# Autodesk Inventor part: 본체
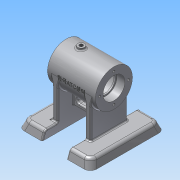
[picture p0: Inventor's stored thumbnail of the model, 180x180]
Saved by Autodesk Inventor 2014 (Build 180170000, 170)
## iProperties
Created: 2016-07
Part Number: 본체
Material: 알루미늄 6061
Document SubType Name: Modeling
Designer: Administrator
Density: 2.71 g/cm^3
Appearance: 알루미늄 - 평지
Mass: 512.163 g
Surface Area: 537.388 cm^2
Volume: 188.99 cm^3
Author: Administrator
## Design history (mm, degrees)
sketch "스케치1"
  geometry: C1 r 27 at (0, 0); 1 further point
  constraints: 1 centre point, 1 coincident
  dimensions: "d0" = 54 diameter of C1
extrude "돌출1" new body sketch "스케치1" stored distance "d1" = 70; taper "d2" = 0 deg
sketch "스케치2"
  geometry: C1 r 22 at (0, 0); 1 further point
  constraints: 1 centre point, 1 coincident
  dimensions: "d3" = 44 diameter of C1
extrude "돌출2" cut sketch "스케치2" stored distance "d4" = 42; taper "d5" = 0 deg
hole "구멍1" diameter "d8" = 32; stored, may be unused: countersink angle "d12" = 90 deg, drill point angle "d14" = 0 deg; dims "d6" = 10, "d7" = 10, "d9" = 6, "d10" = 4, "d11" = 2, "d13" = 12
hole "구멍2" diameter "d17" = 28; stored, may be unused: countersink angle "d21" = 90 deg, drill point angle "d23" = 0 deg; dims "d15" = 10, "d16" = 10, "d18" = 6, "d19" = 4, "d20" = 2, "d22" = 2
fillet "모깎기1" dims "d24" = 0.3
fillet "모깎기2" dims "d25" = 3
node "작업 평면1"
sketch "스케치3"
  geometry: L1 (-27, -35)-(27, -35) reference; C1 r 5 at (0, -13); 1 further point
  constraints: 1 centre point, 1 vertical alignment
  dimensions: "d28" = 22 distance from line of L1 C1.centre; "d29" = 10 diameter of C1
extrude "돌출3" join sketch "스케치3" stored distance "d30" = 42; taper "d31" = 0 deg
hole "구멍3" diameter "d34" = 5.188; stored, may be unused: countersink angle "d38" = 90 deg, drill point angle "d40" = 0 deg; dims "d32" = 10, "d33" = 10, "d35" = 6, "d36" = 4, "d37" = 2, "d39" = 2
sketch "스케치4" dims "d41" = 42
  geometry: C1 r 16 at (0, 0) reference; C2 r 27 at (0, 0) reference; 2 further points
  constraints: 2 vertical alignment, 1 coincident, 2 other
hole "구멍4" sketch "스케치4" at (0, 21) diameter "d42" = 3.242; stored, may be unused: countersink angle "d46" = 90 deg, drill point angle "d48" = 118 deg; dims "d43" = 8, "d44" = 4, "d45" = 2, "d47" = 10
sketch "스케치5"
  geometry: L1 (0, 0)-(0, -55.752); L2 (0, 0)-(15.898, -25.441)
  constraints: 4 end point, 1 vertical
  dimensions: "d52" = 32 deg angle of L1 L2; "d53" = 30 distance of L1.start L2.end
node "작업 평면2"
sketch "스케치6"
  geometry: C1 r 6 at (0, 0); 1 further point
  constraints: 1 centre point, 1 coincident
  dimensions: "d54" = 12 diameter of C1
extrude "돌출4" join sketch "스케치6" stored distance "d55" = 42; taper "d56" = 0 deg
hole "구멍5" diameter "d59" = 5.188; stored, may be unused: countersink angle "d63" = 90 deg, drill point angle "d65" = 0 deg; dims "d57" = 10, "d58" = 10, "d60" = 8, "d61" = 4, "d62" = 2, "d64" = 10
node "작업 평면8"
sketch "스케치17"
  geometry: L1 (27, 0)-(27, -70); L2 (27, -70)-(-27, -70); L3 (-27, -70)-(-27, 0); C1 r 27 at (0, 0) reference; A1 r 27 centre (0, 0) between (-27, 0) and (27, 0); 2 further points
  constraints: 8 end point, 2 point on circle, 1 centre point, 1 coincident, 1 concentric, 1 parallel, 1 vertical alignment
  dimensions: "d113" = 54 distance of L1.end L2.end; "d114" = 70 distance of L2.end L3.end; "d115" = 27 distance from line of point (0, -46.957) L3; "d116" = 46.95708 distance of point (0, 0) point (0, -46.957); "d117" = 70 distance of L1.start L1.end; "d118" = 23.04292 distance from line of L2 point (0, -46.957)
extrude "돌출11" join sketch "스케치17" distance "d119" = 8; taper "d120" = 0 deg
sketch "스케치19"
  geometry: L1 (-27, -70)-(27, -70) reference; L2 (-50, -58)-(50, -58); L3 (50, -58)-(50, -70); L4 (50, -70)-(-50, -70); L5 (-50, -70)-(-50, -58); 1 further point
  constraints: 8 end point, 2 midpoint, 2 parallel, 1 horizontal, 1 perpendicular
  dimensions: "d125" = 12 distance of L2.end L3.end; "d126" = 100 distance of L2.start L2.end
extrude "돌출13" join sketch "스케치19" distance "d127" = 35; taper "d128" = 0 deg
fillet "모깎기4" dims "d129" = 2
feature "면 기울기7" dims angle "d130" = -20 deg
feature "면 기울기8" dims angle "d131" = -20 deg
feature "면 기울기9" dims angle "d132" = -20 deg
fillet "모깎기5" dims "d133" = 2
fillet "모깎기7" dims "d135" = 10
fillet "모깎기9" dims "d137" = 2
feature "면 기울기10" dims angle "d138" = -20 deg
feature "면 기울기11" dims angle "d139" = -20 deg
feature "면 기울기12" dims angle "d140" = -20 deg
fillet "모깎기10" dims "d141" = 10
fillet "모깎기11" dims "d142" = 2
fillet "모깎기12" dims "d143" = 5
fillet "모깎기13" dims "d144" = 2
fillet "모깎기14" dims "d145" = 5
fillet "모깎기15" dims "d146" = 2
sketch "스케치20"
  geometry: L1 (-26, -20)-(-48, -20); L2 (-48, -20)-(-48, 20); L3 (-48, 20)-(-26, 20); L4 (-27, -35)-(-27, 35) reference; L5 (-14.697, -20)-(-56, -20) reference; L6 (-56, 20)-(-14.697, 20) reference; L7 (-26, -20)-(-26, 20); 2 further points
  constraints: 8 end point, 3 parallel, 2 horizontal alignment, 1 horizontal, 1 perpendicular
  dimensions: "d147" = 21 distance between parallel lines of L4 L2; "d148" = 22 distance of L2.end L3.end; "d151" = 40 distance of L1.end L2.end; "d152" = 20.97754 distance from line of L2 point (-27.022, 0)
extrude "돌출14" join sketch "스케치20" stored distance "d149" = 8; taper "d150" = 0 deg
sketch "스케치21"
  geometry: L1 (-22, -70)-(-45.603, -70) reference; L2 (11.5, -34.5)-(-11.5, -34.5); L3 (-11.5, -41.5)-(11.5, -41.5); A1 r 3.5 centre (-11.5, -38) between (-11.5, -34.5) and (-11.5, -41.5); A2 r 3.5 centre (11.5, -38) between (11.5, -34.5) and (11.5, -41.5); 1 further point
  constraints: 4 end point, 4 point on circle, 3 tangent, 2 centre point, 1 horizontal alignment, 1 parallel
  dimensions: "d153" = 11.5 horizontal distance of point (0, 0) A1.centre; "d154" = 32 distance from line of L1 A1.centre; "d155" = 7 diameter of A1; "d156" = 7 diameter of A2; "d157" = 23 distance of A2.centre A1.centre
extrude "돌출15" cut sketch "스케치21" stored distance "d158" = 8; taper "d159" = 0 deg
fillet "모깎기16" dims "d160" = 2
fillet "모깎기17" dims "d161" = 2
node "작업 평면9"
sketch "스케치22"
  geometry: 2 further points
  constraints: 1 coincident, 1 other
feature "엠보싱1" sketch "스케치22" dims "d162" = 0.5, "d163" = 0
node "솔리드1"
mirror "대칭1"
pattern_circular "원형 패턴1" dims angle "d50" = 360 deg
mirror "대칭2"
mirror "대칭5"
